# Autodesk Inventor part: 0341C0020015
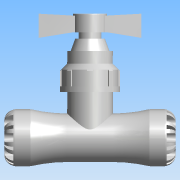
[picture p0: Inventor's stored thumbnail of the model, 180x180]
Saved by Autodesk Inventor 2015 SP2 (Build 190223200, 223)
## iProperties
Created: 2016-12
Part Number: 0341C0020015
Material: PVC-Piping
Description: PLASSON COPPER PIPE ADAPTOR STOPTAP 20-15 SERIES 1
Document SubType Name: Modeling
Designer: KIM
Mass: 61.7504 g
Surface Area: 140.097 cm^2
Volume: 44.1074 cm^3
Density: 1.4 g/cm^3
Appearance: Smooth - White
Author: KIM
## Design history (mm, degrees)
derived "0341C.ipt"
feature "Solid1::0341C.ipt"
feature "Solid2::0341C.ipt"
tag "TaggingFeature1"
body "Solid1"
other parameters: "d1" = 18.9, "d3" = 25, "d4" = 41, "d6" = 45, "d8" = 34.85, "d13" = 6.4, "d14" = 6.4, "d15" = 0, "d17" = 360 deg, "d19" = 8 deg, "d20" = 0.4, "d21" = 0.4, "d22" = 8 deg, "d24" = 0, "d26" = 360 deg, "d33" = 4.1, "d35" = 2.5, "d65" = 0.41, "d69" = 123, "d71" = 15, "d72" = 41, "d73" = 25, "d74" = 18.9, "d75" = 61.5, "d76" = 1.875, "d77" = 45, "d80" = 6.4, "d82" = 6.4, "d83" = 0, "d85" = 360 deg, "d87" = 0.3, "d88" = 8 deg, "d89" = 8 deg, "d90" = 0.3, "d92" = 0, "d94" = 360 deg, "d96" = 89, "d97" = 41, "d98" = 32.8, "d99" = 32.8, "d100" = 135 deg, "d101" = 16.4, "d102" = 70 deg, "d103" = 48.95, "d104" = 71.2, "d105" = 62.3, "d107" = 75.65, "d108" = 73.8, "d110" = 12.015, "d111" = 4.005, "d112" = 12.3, "d113" = 0, "d114" = 43.05, "d115" = 4.1, "d116" = 0, "d117" = 4.1, "d119" = 0, "d121" = 360 deg, "d127" = 0, "d128" = 0.41, "E_" = 41, "H_" = 123, "l_" = 45, "A_" = 89, "l_1" = 45, "d_1" = 15, "E_1" = 41, "d9" = 8, "d11" = 41, "d12" = 25, "d78" = 41, "d79" = 25, "d81" = 8, "d109" = 13.35
